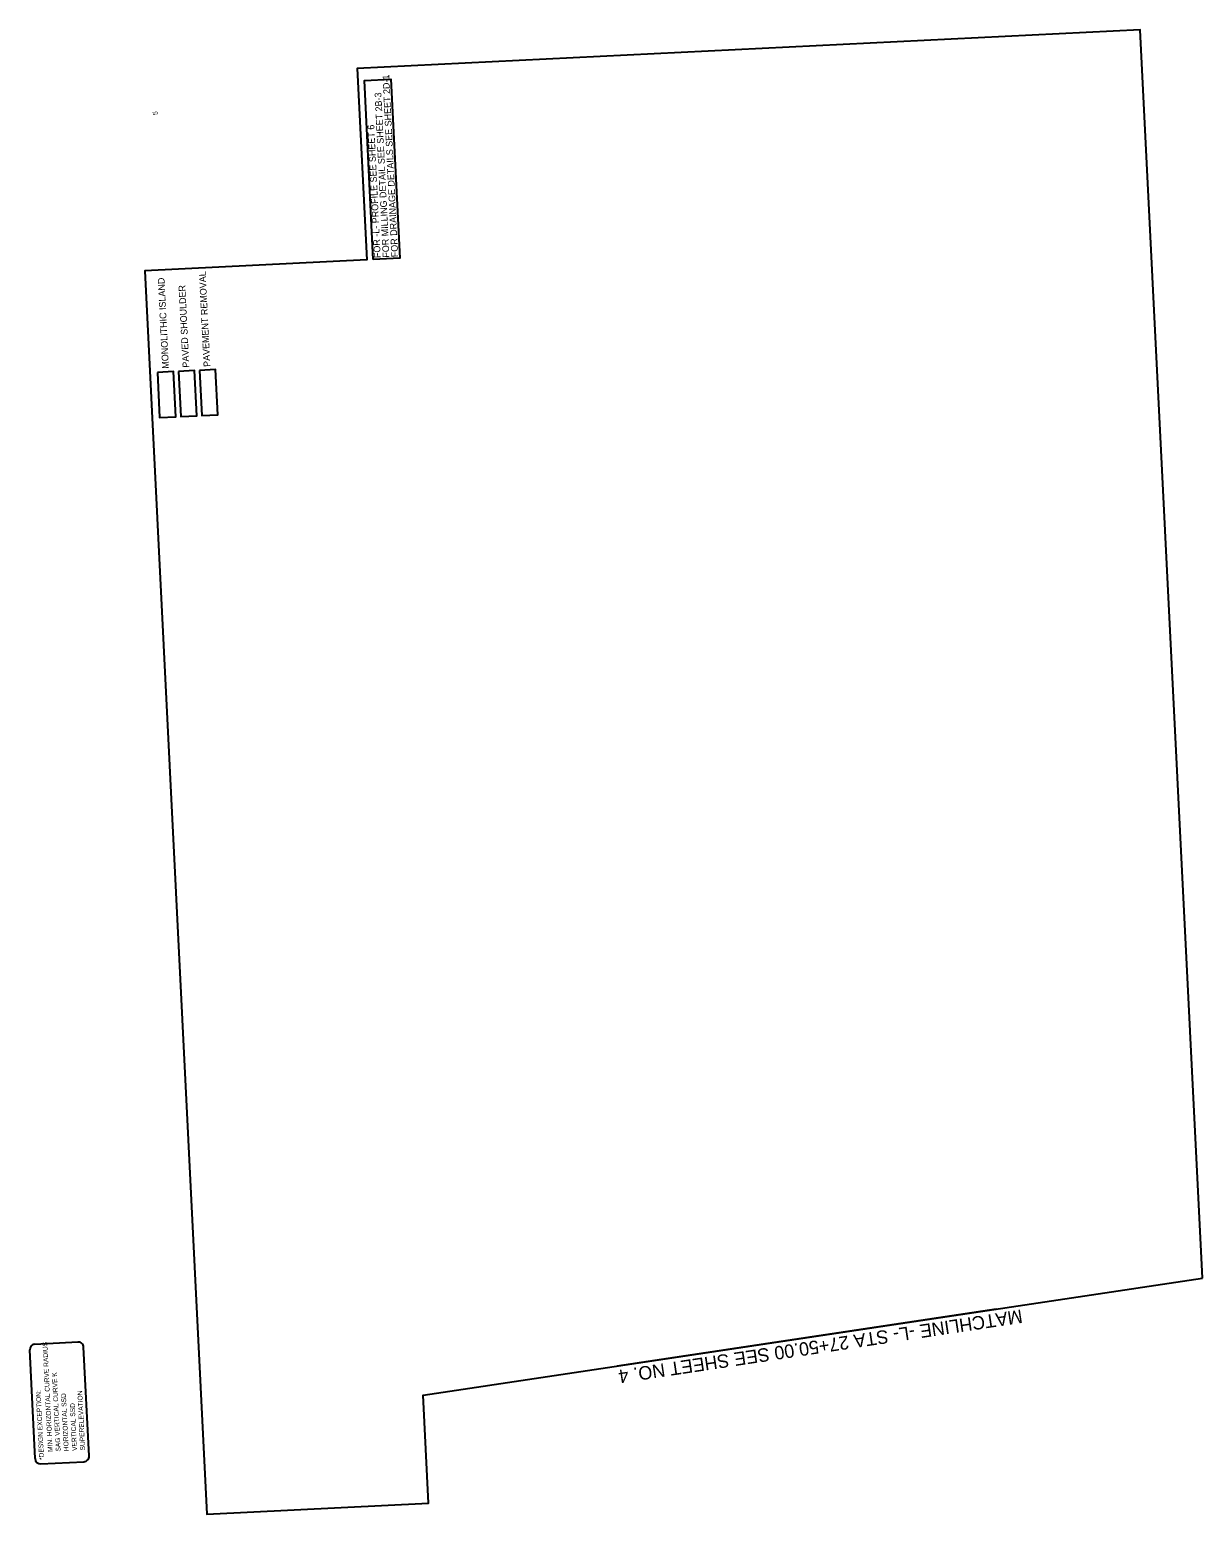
# Model space of a CAD drawing. Extents: x 1807033 to 1808257, y 915068 to 916618.
import ezdxf

# ---------------------------------------------------------------- set-up
doc = ezdxf.new("R2010")
doc.units = 0
for name, color, linetype in [('Exist Drainage Structure Drop Inlet CELL', 7, 'Continuous'), ('Old_Level_18', 7, 'Continuous'), ('Old_Level_2', 7, 'Continuous'), ('Old_Level_38', 7, 'Continuous'), ('Old_Level_44', 7, 'Continuous'), ('Prop Drainage Structure Drop Inlet Grate 2 Narrow Slots and Flat Grates 840 29 TB CELL', 7, 'Continuous'), ('Prop Drainage Structure Plot Symbol 50 Scale', 7, 'Continuous'), ('Prop DSN Text', 7, 'Continuous'), ('Prop Erosion Rip Rap Pad at Outlet CELL', 7, 'Continuous'), ('Scratch_Level_3', 7, 'Continuous'), ('Scratch_Level_5', 7, 'Continuous')]:
    doc.layers.add(name, color=color, linetype=linetype)

msp = doc.modelspace()

# ---------------------------------------------------------------- linework, layer by layer
at = {"layer": 'Exist Drainage Structure Drop Inlet CELL'}
msp.add_lwpolyline([(1807166.7, 916260.5), (1807169, 916213.3), (1807186, 916214.1), (1807183.6, 916261.4), (1807166.7, 916260.5)], dxfattribs=at)
at = {"layer": 'Old_Level_18'}
for p, q in [((1807039, 915126.3), (1807033.4, 915239.9)), ((1807038.8, 915245.9), (1807083.7, 915248.2)), ((1807095.4, 915129.1), (1807089.7, 915242.7)), ((1807045, 915120.9), (1807090, 915123.1))]:
    msp.add_line(p, q, dxfattribs=at)
for centre, start, end in [((1807039.1, 915240.2), 92.8422, 182.8422), ((1807084, 915242.4), 2.8422, 92.8422), ((1807044.7, 915126.6), 182.8422, 272.8422), ((1807089.7, 915128.8), 272.8422, 2.8422)]:
    msp.add_arc(centre, 5.71, start, end, dxfattribs=at)
at = {"layer": 'Old_Level_2'}
msp.add_lwpolyline([(1808257.3, 915314.8), (1808192.5, 916618.4), (1807375.2, 916577.8), (1807385.1, 916378), (1807153.7, 916366.5), (1807218.2, 915068.2), (1807449.6, 915079.7), (1807444, 915192.5)], close=True, dxfattribs=at)
at = {"layer": 'Prop Drainage Structure Drop Inlet Grate 2 Narrow Slots and Flat Grates 840 29 TB CELL'}
msp.add_lwpolyline([(1807392, 916378.4), (1807382.7, 916565.4), (1807410.3, 916566.8), (1807419.6, 916379.7)], close=True, dxfattribs=at)
at = {"layer": 'Prop DSN Text'}
msp.add_line((1808042, 915282.4), (1807646.4, 915222.9), dxfattribs=at)
at = {"layer": 'Prop Erosion Rip Rap Pad at Outlet CELL'}
msp.add_lwpolyline([(1807188.6, 916261.6), (1807191, 916214.4), (1807207.9, 916215.2), (1807205.5, 916262.5), (1807188.6, 916261.6)], dxfattribs=at)
msp.add_lwpolyline([(1807188.6, 916261.6), (1807191, 916214.4), (1807207.9, 916215.2), (1807205.5, 916262.5)], close=True, dxfattribs=at)
at = {"layer": 'Scratch_Level_5'}
for points in [[(1807166.7, 916260.5), (1807169, 916213.3), (1807186, 916214.1), (1807183.6, 916261.4)], [(1807188.6, 916261.6), (1807191, 916214.4), (1807207.9, 916215.2), (1807205.5, 916262.5)], [(1807210.5, 916262.7), (1807212.9, 916215.5), (1807229.8, 916216.3), (1807227.4, 916263.6)]]:
    msp.add_lwpolyline(points, close=True, dxfattribs=at)
msp.add_lwpolyline([(1807188.6, 916261.6), (1807191, 916214.4), (1807207.9, 916215.2), (1807205.5, 916262.5), (1807188.6, 916261.6)], dxfattribs=at)

# ---------------------------------------------------------------- texts
at = {"layer": 'Old_Level_38'}
for s, p in [('MIN. HORIZONTAL CURVE RADIUS', (1807057.4, 915133.4)), ('SAG VERTICAL CURVE K', (1807065.7, 915133.8)), ('*DESIGN EXCEPTION: ', (1807048.3, 915125.1)), ('HORIZONTAL SSD', (1807074.1, 915134.2)), ('SUPERELEVATION', (1807091.2, 915135)), ('VERTICAL SSD', (1807082.8, 915134.6))]:
    msp.add_text(s, height=5, rotation=92.8372, dxfattribs=at).set_placement(p)
at = {"layer": 'Old_Level_44'}
msp.add_text('5', height=5, rotation=92.8422, dxfattribs=at).set_placement((1807167, 916529.5))
at = {"layer": 'Prop Drainage Structure Plot Symbol 50 Scale'}
msp.add_text('MATCHLINE -L- STA 27+50.00 SEE SHEET NO. 4', height=14, rotation=188.5557, dxfattribs=at).set_placement((1808068.4, 915282.1))
at = {"layer": 'Scratch_Level_3'}
for s, rotation, p in [('FOR DRAINAGE DETAILS SEE SHEET 2D-1', 92.8419, (1807418, 916381)), ('FOR MILLING DETAIL SEE SHEET 2B-3', 92.8419, (1807408.9, 916380.5)), ('FOR -L- PROFILE SEE SHEET 6', 92.8419, (1807399.8, 916380.1)), ('PAVEMENT REMOVAL', 92.8422, (1807221.9, 916266.5)), ('MONOLITHIC ISLAND', 92.8422, (1807178.7, 916264.6)), ('PAVED SHOULDER', 92.8422, (1807200, 916265.7))]:
    msp.add_text(s, height=7, rotation=rotation, dxfattribs=at).set_placement(p)

doc.saveas('drawing.dxf')
